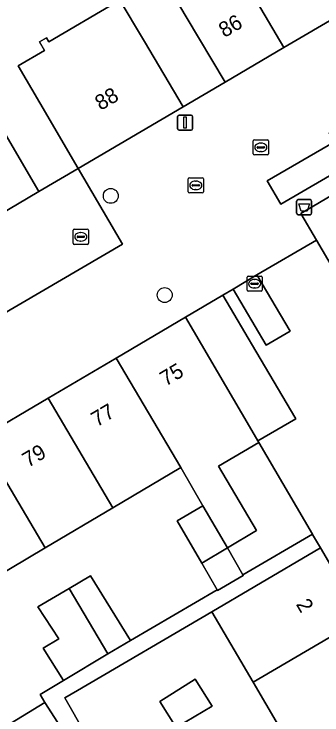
# Model space of a CAD drawing. Extents: x 161771 to 163125, y 382475 to 383179.
# Drawn here: x 162234.66 to 162254.94, y 382779.88 to 382825.98 of the extents above; entities that cross this region are included whole.
import ezdxf

# ---------------------------------------------------------------- set-up
doc = ezdxf.new("R2010")
doc.units = 0
for name, color, linetype in [('IMGEO_Afvalbak', 7, 'Continuous'), ('IMGEO_Boom', 7, 'Continuous'), ('IMGEO_Erf', 7, 'Continuous'), ('IMGEO_Kolk', 7, 'Continuous'), ('IMGEO_Lichtmast', 7, 'Continuous'), ('IMGEO_Muur', 7, 'Continuous'), ('IMGEO_Pand', 7, 'Continuous'), ('IMGEO_Pand_nummerreeks', 7, 'Continuous'), ('IMGEO_Parkeervlak_open', 7, 'Continuous'), ('IMGEO_Rioolput', 7, 'Continuous'), ('IMGEO_Voetpad_open', 7, 'Continuous'), ('IMGEO_Woonerf_open', 7, 'Continuous')]:
    doc.layers.add(name, color=color, linetype=linetype)

msp = doc.modelspace()

# ---------------------------------------------------------------- linework, layer by layer
at = {"layer": 'IMGEO_Afvalbak'}
for p, q in [((162253.268, 382812.874), (162253.268, 382813.674)), ((162253.268, 382813.674), (162253.268, 382812.874)), ((162253.368, 382813.774), (162254.158, 382813.774)), ((162254.158, 382813.774), (162253.368, 382813.774)), ((162254.258, 382813.674), (162254.258, 382812.874)), ((162254.258, 382812.874), (162254.258, 382813.674)), ((162254.158, 382812.774), (162253.368, 382812.774)), ((162253.368, 382812.774), (162254.158, 382812.774))]:
    msp.add_line(p, q, dxfattribs=at)
msp.add_lwpolyline([(162253.411, 382813.488), (162254.115, 382813.488), (162253.966, 382813.018), (162253.56, 382813.018), (162253.411, 382813.488)], dxfattribs=at)
for centre, start, end in [((162253.368, 382813.674), 90, 180), ((162253.368, 382813.674), 90, 180), ((162254.158, 382813.674), 0, 90), ((162254.158, 382813.674), 360, 90), ((162253.368, 382812.874), 180, 270), ((162253.368, 382812.874), 180, 270), ((162254.158, 382812.874), 270, 0), ((162254.158, 382812.874), 270, 0)]:
    msp.add_arc(centre, 0.1, start, end, dxfattribs=at)
at = {"layer": 'IMGEO_Boom'}
for centre in [(162241.036, 382814.018), (162244.586, 382807.493)]:
    msp.add_circle(centre, 0.489, dxfattribs=at)
at = {"layer": 'IMGEO_Erf'}
for points in [[(162233.77, 382818.622), (162236.304, 382814.311), (162238.887, 382815.82), (162236.358, 382820.134), (162234.934, 382822.564), (162236.668, 382823.577), (162236.339, 382824.148), (162236.794, 382824.415), (162236.949, 382824.151), (162241.363, 382826.738), (162241.256, 382826.921), (162241.519, 382827.076), (162240.025, 382829.477), (162237.911, 382828.166), (162236.769, 382829.009), (162237.852, 382831.132), (162238.913, 382831.272), (162232.428, 382841.879)], [(162232.26, 382778.007), (162236.7, 382780.702), (162236.383, 382781.224), (162237.921, 382782.157), (162236.579, 382784.272), (162237.616, 382784.876), (162236.226, 382786.998), (162238.289, 382788.201), (162239.705, 382789.026), (162242.33, 382784.778), (162248.038, 382788.108), (162247.017, 382789.867), (162245.405, 382792.645), (162247.1, 382793.644), (162245.644, 382796.155), (162241.178, 382793.508), (162236.713, 382790.862), (162232.247, 382788.215), (162232.091, 382788.123), (162233.565, 382785.636), (162229.254, 382783.082), (162224.789, 382780.437), (162222.067, 382778.825)], [(162253.067, 382777.508), (162250.409, 382782.028), (162247.679, 382786.671), (162238.839, 382781.491), (162238.013, 382781.007), (162240.694, 382776.324)]]:
    msp.add_lwpolyline(points, dxfattribs=at)
for points in [[(162250.783, 382797.804), (162248.121, 382796.245), (162250.632, 382792.008), (162248.709, 382790.869), (162249.736, 382789.098), (162254.304, 382791.763)], [(162245.34, 382779.059), (162244.264, 382780.76), (162246.586, 382782.23), (162247.713, 382780.449)]]:
    msp.add_lwpolyline(points, close=True, dxfattribs=at)
at = {"layer": 'IMGEO_Kolk'}
for p, q in [((162250.413, 382816.78), (162250.413, 382817.632)), ((162250.488, 382817.706), (162251.34, 382817.706)), ((162251.414, 382817.632), (162251.414, 382816.78)), ((162250.672, 382817.2), (162250.672, 382817.212)), ((162251.11, 382817.163), (162250.712, 382817.163)), ((162250.715, 382817.249), (162251.113, 382817.249)), ((162250.901, 382817.486), (162250.926, 382817.486)), ((162251.156, 382817.212), (162251.156, 382817.2)), ((162251.34, 382816.706), (162250.488, 382816.706)), ((162250.924, 382816.926), (162250.899, 382816.926)), ((162238.559, 382810.9), (162238.559, 382811.752)), ((162238.634, 382811.826), (162239.486, 382811.826)), ((162239.047, 382811.606), (162239.072, 382811.606)), ((162239.56, 382811.752), (162239.56, 382810.9)), ((162238.818, 382811.32), (162238.818, 382811.332)), ((162239.256, 382811.283), (162238.858, 382811.283)), ((162238.861, 382811.369), (162239.259, 382811.369)), ((162239.302, 382811.332), (162239.302, 382811.32)), ((162239.486, 382810.826), (162238.634, 382810.826)), ((162239.07, 382811.046), (162239.045, 382811.046)), ((162250.003, 382807.815), (162250.003, 382808.667)), ((162250.078, 382808.741), (162250.93, 382808.741)), ((162250.491, 382808.521), (162250.516, 382808.521)), ((162251.004, 382808.667), (162251.004, 382807.815)), ((162250.262, 382808.235), (162250.262, 382808.247)), ((162250.7, 382808.198), (162250.302, 382808.198)), ((162250.305, 382808.284), (162250.703, 382808.284)), ((162250.514, 382807.961), (162250.489, 382807.961)), ((162250.746, 382808.247), (162250.746, 382808.235)), ((162250.93, 382807.741), (162250.078, 382807.741))]:
    msp.add_line(p, q, dxfattribs=at)
for points in [[(162250.413, 382816.78), (162250.413, 382817.632)], [(162250.488, 382817.706), (162251.34, 382817.706)], [(162251.414, 382817.632), (162251.414, 382816.78)], [(162251.34, 382816.706), (162250.488, 382816.706)], [(162238.559, 382810.9), (162238.559, 382811.752)], [(162238.634, 382811.826), (162239.486, 382811.826)], [(162239.56, 382811.752), (162239.56, 382810.9)], [(162239.486, 382810.826), (162238.634, 382810.826)], [(162250.003, 382807.815), (162250.003, 382808.667)], [(162250.078, 382808.741), (162250.93, 382808.741)], [(162251.004, 382808.667), (162251.004, 382807.815)], [(162250.93, 382807.741), (162250.078, 382807.741)]]:
    msp.add_lwpolyline(points, dxfattribs=at)
for centre, radius, start, end in [((162250.49, 382817.63), 0.0765, 91.552, 178.448), ((162250.49, 382817.63), 0.0765, 91.552, 178.448), ((162251.338, 382817.63), 0.0765, 1.552, 88.448), ((162251.338, 382817.63), 0.0765, 1.552, 88.448), ((162250.712, 382817.209), 0.0403, 85.8775, 175.7526), ((162250.709, 382817.199), 0.0366, 178.938, 274.7102), ((162251.113, 382817.206), 0.043, 264.8664, 352.4533), ((162251.117, 382817.211), 0.0386, 1.7309, 96.639), ((162250.49, 382816.782), 0.0765, 181.552, 268.448), ((162250.49, 382816.782), 0.0765, 181.552, 268.448), ((162251.338, 382816.782), 0.0765, 271.552, 358.448), ((162251.338, 382816.782), 0.0765, 271.552, 358.448), ((162238.636, 382811.75), 0.0765, 91.552, 178.448), ((162238.636, 382811.75), 0.0765, 91.552, 178.448), ((162239.484, 382811.75), 0.0765, 1.552, 88.448), ((162239.484, 382811.75), 0.0765, 1.552, 88.448), ((162238.858, 382811.329), 0.0403, 85.8775, 175.7526), ((162238.855, 382811.319), 0.0366, 178.938, 274.7102), ((162239.259, 382811.326), 0.043, 264.8664, 352.4533), ((162239.263, 382811.331), 0.0386, 1.7309, 96.639), ((162238.636, 382810.902), 0.0765, 181.552, 268.448), ((162238.636, 382810.902), 0.0765, 181.552, 268.448), ((162239.484, 382810.902), 0.0765, 271.552, 358.448), ((162239.484, 382810.902), 0.0765, 271.552, 358.448), ((162250.08, 382808.665), 0.0765, 91.552, 178.448), ((162250.08, 382808.665), 0.0765, 91.552, 178.448), ((162250.928, 382808.665), 0.0765, 1.552, 88.448), ((162250.928, 382808.665), 0.0765, 1.552, 88.448), ((162250.302, 382808.244), 0.0403, 85.8775, 175.7526), ((162250.299, 382808.234), 0.0366, 178.938, 274.7102), ((162250.703, 382808.241), 0.043, 264.8664, 352.4533), ((162250.707, 382808.246), 0.0386, 1.7309, 96.639), ((162250.08, 382807.817), 0.0765, 181.552, 268.448), ((162250.08, 382807.817), 0.0765, 181.552, 268.448), ((162250.928, 382807.817), 0.0765, 271.552, 358.448), ((162250.928, 382807.817), 0.0765, 271.552, 358.448)]:
    msp.add_arc(centre, radius, start, end, dxfattribs=at)
for centre, major_axis, ratio, start_param, end_param in [((162250.9, 382817.206), (-0.387, 0.002), 0.722429, 4.712389, 7.853982), ((162250.925, 382817.206), (-0.39, 0.002), 0.717154, 1.570796, 4.712389), ((162239.046, 382811.326), (-0.387, 0.002), 0.722429, 4.712389, 7.853982), ((162239.071, 382811.326), (-0.39, 0.002), 0.717154, 1.570796, 4.712389), ((162250.49, 382808.241), (-0.387, 0.002), 0.722429, 4.712389, 7.853982), ((162250.515, 382808.241), (-0.39, 0.002), 0.717154, 1.570796, 4.712389)]:
    msp.add_ellipse(centre, major_axis=major_axis, ratio=ratio, start_param=start_param, end_param=end_param, dxfattribs=at)
at = {"layer": 'IMGEO_Lichtmast'}
for p, q in [((162245.432, 382818.435), (162245.432, 382819.235)), ((162245.432, 382819.235), (162245.432, 382818.435)), ((162245.532, 382819.335), (162246.322, 382819.335)), ((162246.322, 382819.335), (162245.532, 382819.335)), ((162246.422, 382819.235), (162246.422, 382818.435)), ((162246.422, 382818.435), (162246.422, 382819.235)), ((162246.322, 382818.335), (162245.532, 382818.335)), ((162245.532, 382818.335), (162246.322, 382818.335))]:
    msp.add_line(p, q, dxfattribs=at)
msp.add_lwpolyline([(162245.852, 382819.21), (162246.002, 382819.21), (162246.002, 382818.46), (162245.852, 382818.46), (162245.852, 382819.21)], dxfattribs=at)
for centre, start, end in [((162245.532, 382819.235), 90, 180), ((162245.532, 382819.235), 90, 180), ((162246.322, 382819.235), 0, 90), ((162246.322, 382819.235), 360, 90), ((162245.532, 382818.435), 180, 270), ((162245.532, 382818.435), 180, 270), ((162246.322, 382818.435), 270, 0), ((162246.322, 382818.435), 270, 0)]:
    msp.add_arc(centre, 0.1, start, end, dxfattribs=at)
at = {"layer": 'IMGEO_Muur'}
for points in [[(162236.304, 382814.311), (162238.887, 382815.82)], [(162250.176, 382798.84), (162254.311, 382791.751)]]:
    msp.add_lwpolyline(points, dxfattribs=at)
at = {"layer": 'IMGEO_Pand'}
for points in [[(162252.159, 382832.923), (162252.016, 382833.167), (162250.262, 382832.14), (162249.493, 382833.452), (162246.824, 382838.005), (162246.064, 382837.559), (162244.977, 382836.922), (162244.758, 382836.794), (162245.431, 382835.65), (162252.42, 382823.768), (162256.216, 382825.999)], [(162245.431, 382835.65), (162243.639, 382834.599), (162246.557, 382829.619), (162244.462, 382828.391), (162246.006, 382825.799), (162248.564, 382821.502), (162252.42, 382823.768)], [(162245.808, 382819.868), (162243.251, 382824.165), (162241.519, 382827.076), (162241.256, 382826.921), (162241.363, 382826.738), (162236.949, 382824.151), (162236.794, 382824.415), (162236.339, 382824.148), (162236.668, 382823.577), (162234.934, 382822.564), (162236.358, 382820.134), (162238.887, 382815.82)], [(162233.77, 382818.622), (162233.686, 382818.765), (162233.619, 382818.879), (162226.584, 382814.737), (162229.285, 382810.148), (162230.884, 382811.096), (162236.304, 382814.311)], [(162256.216, 382808.295), (162263.113, 382812.329), (162262.958, 382812.596), (162260.443, 382816.917), (162253.545, 382812.855), (162254.568, 382811.108)], [(162250.176, 382798.84), (162245.956, 382806.045), (162241.383, 382803.349), (162245.644, 382796.155), (162247.1, 382793.644), (162248.709, 382790.869), (162250.632, 382792.008), (162248.121, 382796.245), (162250.783, 382797.804), (162250.723, 382797.907)], [(162241.383, 382803.349), (162236.911, 382800.713), (162241.178, 382793.508), (162245.644, 382796.155)], [(162241.178, 382793.508), (162236.911, 382800.713), (162232.439, 382798.077), (162236.713, 382790.862)], [(162229.344, 382792.754), (162229.544, 382792.779), (162232.247, 382788.215), (162236.713, 382790.862), (162232.439, 382798.077), (162227.846, 382795.37)], [(162248.709, 382790.869), (162247.1, 382793.644), (162245.405, 382792.645), (162247.017, 382789.867)], [(162248.709, 382790.869), (162247.017, 382789.867), (162248.038, 382788.108), (162248.057, 382788.075), (162249.757, 382789.062), (162249.736, 382789.098)], [(162250.409, 382782.028), (162257.56, 382786.216), (162254.83, 382790.861), (162250.517, 382788.334), (162247.679, 382786.671)], [(162238.289, 382788.201), (162240.841, 382783.893), (162242.33, 382784.778), (162239.705, 382789.026)], [(162238.289, 382788.201), (162236.226, 382786.998), (162237.616, 382784.876), (162236.579, 382784.272), (162237.921, 382782.157), (162240.841, 382783.893)], [(162250.409, 382782.028), (162253.067, 382777.508), (162260.217, 382781.695), (162257.56, 382786.216)], [(162247.713, 382780.449), (162246.586, 382782.23), (162244.264, 382780.76), (162245.34, 382779.059)], [(162233.4, 382776.083), (162237.919, 382778.787), (162236.7, 382780.702), (162232.26, 382778.007)]]:
    msp.add_lwpolyline(points, close=True, dxfattribs=at)
at = {"layer": 'IMGEO_Parkeervlak_open'}
for points in [[(162256.638, 382816.047), (162255.752, 382817.574), (162251.339, 382815.015), (162252.229, 382813.481)], [(162238.887, 382815.82), (162236.304, 382814.311), (162230.884, 382811.096), (162233.78, 382806.145), (162241.801, 382810.837)], [(162249.087, 382807.891), (162251.264, 382804.198), (162252.834, 382805.124), (162250.657, 382808.817)], [(162250.593, 382803.802), (162248.416, 382807.495), (162245.956, 382806.045), (162250.176, 382798.84), (162250.723, 382797.907), (162253.212, 382799.36)]]:
    msp.add_lwpolyline(points, close=True, dxfattribs=at)
at = {"layer": 'IMGEO_Rioolput'}
for p, q in [((162246.131, 382814.284), (162246.131, 382815.136)), ((162246.206, 382815.21), (162247.058, 382815.21)), ((162246.619, 382814.99), (162246.644, 382814.99)), ((162247.132, 382815.136), (162247.132, 382814.284)), ((162246.39, 382814.704), (162246.39, 382814.716)), ((162246.828, 382814.667), (162246.43, 382814.667)), ((162246.433, 382814.753), (162246.831, 382814.753)), ((162246.642, 382814.43), (162246.617, 382814.43)), ((162246.874, 382814.716), (162246.874, 382814.704)), ((162247.058, 382814.21), (162246.206, 382814.21))]:
    msp.add_line(p, q, dxfattribs=at)
for points in [[(162246.131, 382814.284), (162246.131, 382815.136)], [(162246.206, 382815.21), (162247.058, 382815.21)], [(162247.132, 382815.136), (162247.132, 382814.284)], [(162247.058, 382814.21), (162246.206, 382814.21)]]:
    msp.add_lwpolyline(points, dxfattribs=at)
for centre, radius, start, end in [((162246.208, 382815.134), 0.0765, 91.552, 178.448), ((162246.208, 382815.134), 0.0765, 91.552, 178.448), ((162247.056, 382815.134), 0.0765, 1.552, 88.448), ((162247.056, 382815.134), 0.0765, 1.552, 88.448), ((162246.43, 382814.713), 0.0403, 85.8775, 175.7526), ((162246.427, 382814.703), 0.0366, 178.938, 274.7102), ((162246.831, 382814.71), 0.043, 264.8664, 352.4533), ((162246.835, 382814.715), 0.0386, 1.7309, 96.639), ((162246.208, 382814.286), 0.0765, 181.552, 268.448), ((162246.208, 382814.286), 0.0765, 181.552, 268.448), ((162247.056, 382814.286), 0.0765, 271.552, 358.448), ((162247.056, 382814.286), 0.0765, 271.552, 358.448)]:
    msp.add_arc(centre, radius, start, end, dxfattribs=at)
for centre, major_axis, ratio, start_param, end_param in [((162246.618, 382814.71), (-0.387, 0.002), 0.722429, 4.712389, 7.853982), ((162246.643, 382814.71), (-0.39, 0.002), 0.717154, 1.570796, 4.712389)]:
    msp.add_ellipse(centre, major_axis=major_axis, ratio=ratio, start_param=start_param, end_param=end_param, dxfattribs=at)
at = {"layer": 'IMGEO_Voetpad_open'}
for points in [[(162232.428, 382841.879), (162238.913, 382831.272), (162240.025, 382829.477), (162241.519, 382827.076), (162243.251, 382824.165), (162245.808, 382819.868), (162248.564, 382821.502), (162246.006, 382825.799), (162244.462, 382828.391), (162236.353, 382841.53), (162240.502, 382844.114), (162243.402, 382845.774), (162244.973, 382846.658), (162248.12, 382848.526), (162251.109, 382850.3), (162253.183, 382851.642), (162255.93, 382853.3), (162258.316, 382854.74), (162260.336, 382855.972), (162260.269, 382856.083), (162263.165, 382857.831), (162263.223, 382857.735), (162264.493, 382858.463)], [(162240.694, 382776.324), (162238.013, 382781.007), (162238.839, 382781.491), (162247.679, 382786.671), (162250.517, 382788.334), (162254.83, 382790.861), (162254.311, 382791.751), (162254.304, 382791.763), (162249.736, 382789.098), (162249.757, 382789.062), (162248.057, 382788.075), (162248.038, 382788.108), (162242.33, 382784.778), (162240.841, 382783.893), (162237.921, 382782.157), (162236.383, 382781.224), (162236.7, 382780.702), (162237.919, 382778.787)]]:
    msp.add_lwpolyline(points, dxfattribs=at)
at = {"layer": 'IMGEO_Woonerf_open'}
for points in [[(162284.383, 382842.553), (162283.477, 382842.022), (162279.427, 382839.641), (162275.547, 382837.361), (162271.667, 382835.081), (162267.788, 382832.801), (162263.908, 382830.52), (162260.009, 382828.229), (162256.216, 382825.999), (162252.42, 382823.768), (162248.564, 382821.502), (162245.808, 382819.868), (162238.887, 382815.82), (162241.801, 382810.837), (162233.78, 382806.145), (162230.884, 382811.096), (162229.285, 382810.148), (162222.787, 382806.395)], [(162209.001, 382778.957), (162208.186, 382780.333), (162211.552, 382782.301), (162211.009, 382783.377), (162211.617, 382785.721), (162227.846, 382795.37), (162232.439, 382798.077), (162236.911, 382800.713), (162241.383, 382803.349), (162245.956, 382806.045), (162248.416, 382807.495), (162249.087, 382807.891), (162250.657, 382808.817), (162254.568, 382811.108), (162253.545, 382812.855), (162260.443, 382816.917), (162262.824, 382818.309), (162265.251, 382819.732)], [(162256.216, 382808.295), (162254.568, 382811.108), (162250.657, 382808.817), (162252.834, 382805.124), (162251.264, 382804.198), (162249.087, 382807.891), (162248.416, 382807.495), (162250.593, 382803.802), (162253.212, 382799.36), (162250.723, 382797.907), (162250.783, 382797.804), (162254.304, 382791.763), (162254.311, 382791.751), (162254.83, 382790.861), (162257.56, 382786.216)]]:
    msp.add_lwpolyline(points, dxfattribs=at)
msp.add_lwpolyline([(162257.266, 382820.401), (162258.836, 382821.281), (162259.717, 382819.712), (162258.147, 382818.831), (162258.953, 382817.394), (162256.638, 382816.047), (162252.229, 382813.481), (162251.339, 382815.015), (162255.752, 382817.574), (162255.409, 382818.166), (162257.668, 382819.433), (162257.775, 382819.493)], close=True, dxfattribs=at)

# ---------------------------------------------------------------- texts
at = {"layer": 'IMGEO_Pand_nummerreeks'}
for s, rotation, p in [('86', 30.4447, (162248.514, 382824.395)), ('88', 30.3228, (162240.364, 382819.603)), ('75', 30.5157, (162244.646, 382801.465)), ('77', 30.5174, (162240.118, 382798.797)), ('79', 30.5174, (162235.591, 382796.128)), ('2', 300.4413, (162253.199, 382787.163))]:
    msp.add_text(s, height=1, rotation=rotation, dxfattribs=at).set_placement(p)

doc.saveas('drawing.dxf')
